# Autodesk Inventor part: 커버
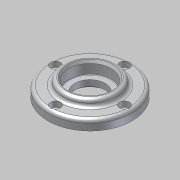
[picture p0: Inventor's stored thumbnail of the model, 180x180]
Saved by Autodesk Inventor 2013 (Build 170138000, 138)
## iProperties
Created: 2014-03
Part Number: 커버
Document SubType Name: Modeling
Designer: SeoGD™[esajin.kr]
Density: 1 g/cm^3
Material: 일반
d0: 6.000 mm
d1: 0.00 deg
d2: 3.000 mm
d3: 0.00 deg
d4: 3.400 mm
d6: 6.000 mm
d7: 3.300 mm
d11: 32.000 mm
d12: 4.000 mm
d13: 0.00 deg
d14: 2.000 mm
d17: 18.000 mm
d19: 25.000 mm
d20: 7.500 mm
d27: 4.000 ul
d28: 360.00 deg
d30: 1.600 mm
d32: 30.00 deg
d33: 0.300 mm
d34: 23.000 mm
d35: 2.000 mm
d36: 0.00 deg
d37: 3.000 mm
d38: 0.500 mm
Author: SeoGD™[esajin.kr]
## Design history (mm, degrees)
sketch "스케치1"
  geometry: C1 r 25 at (0, 0) reference; C2 r 16 at (0, 0) reference; 1 further point
  node "참조1"
  node "참조2"
extrude "돌출1" new body sketch "스케치1" distance "d0" = 6; taper "d1" = 0 deg
extrude "돌출2" join sketch "스케치1" distance "d2" = 3; taper "d3" = 0 deg
sketch "스케치2"
  geometry: C1 r 1.23 at (0, 20.5) reference; 1 further point
hole "구멍1" sketch "스케치2" at (0, 20.5) diameter "d4" = 3.4; stored, may be unused: countersink angle "d8" = 90 deg, drill point angle "d10" = 118 deg; dims "d5" = 6, "d6" = 6, "d7" = 3.3, "d9" = 8
sketch "스케치3"
  geometry: C1 r 16 at (0, 0); 1 further point
  constraints: 1 centre point, 1 coincident
  dimensions: "d11" = 32 diameter of C1
extrude "돌출3" join sketch "스케치3" distance "d12" = 4; taper "d13" = 0 deg
fillet "모깎기1" dims "d14" = 2
hole "구멍2" diameter "d17" = 18; stored, may be unused: countersink angle "d21" = 90 deg, drill point angle "d23" = 118 deg; dims "d15" = 10, "d16" = 10, "d18" = 6, "d19" = 25, "d20" = 7.5, "d22" = 8
chamfer "모따기1" distance "d30" = 1.6; stored, may be unused: second distance "d31" = 2, angle "d32" = 30 deg
fillet "모깎기2" dims "d33" = 0.3
sketch "스케치4"
  geometry: C1 r 16 at (0, 0) reference; C2 r 11.5 at (0, 0); 1 further point
  constraints: 1 centre point, 1 coincident
  dimensions: "d34" = 23 diameter of C2
extrude "돌출4" cut sketch "스케치4" distance "d35" = 2; taper "d36" = 0 deg
fillet "모깎기3" dims "d37" = 3
chamfer "모따기2" distance "d38" = 0.5; stored, may be unused: second distance "d39" = 2, angle "d40" = 45 deg
node "솔리드1"
pattern_circular "원형 패턴2" dims count "d27" = 4, angle "d28" = 360 deg
node "참조3"
